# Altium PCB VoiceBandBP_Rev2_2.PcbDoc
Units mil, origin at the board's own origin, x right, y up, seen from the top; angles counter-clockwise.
Board outline 2300 x 3500 mil, 2 copper layers (Top Layer, Bottom Layer), stack 62 mil thick; 53 components, 66 nets, 172 pads, 192 vias.
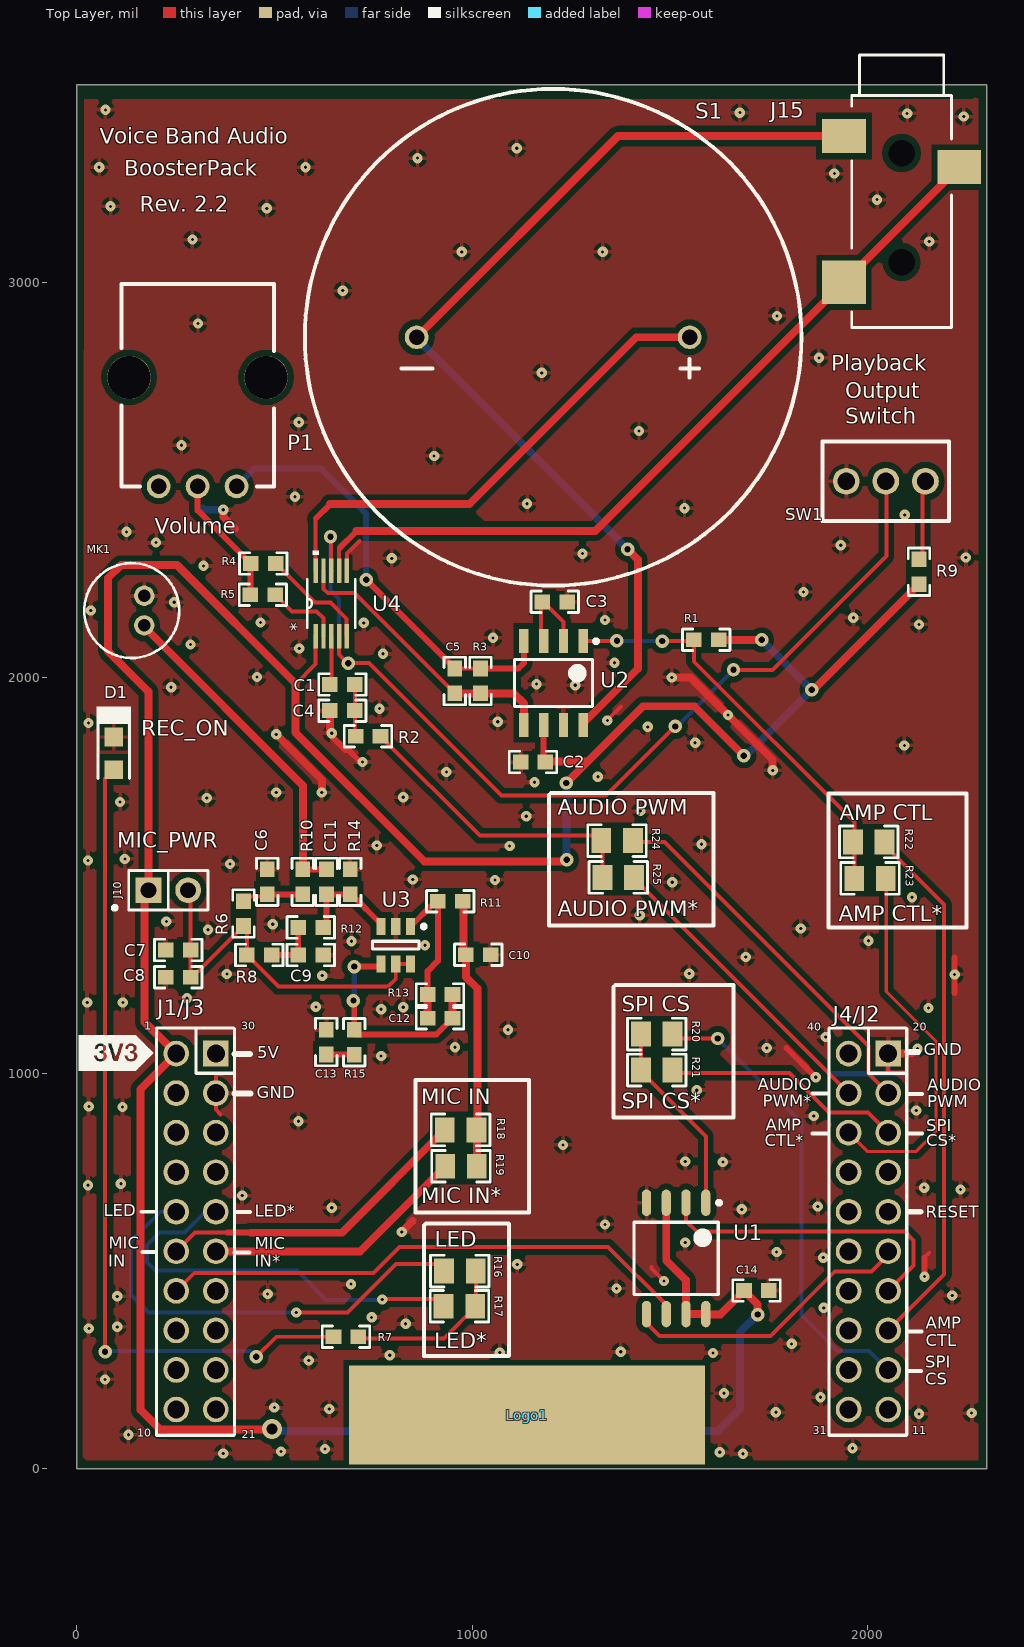
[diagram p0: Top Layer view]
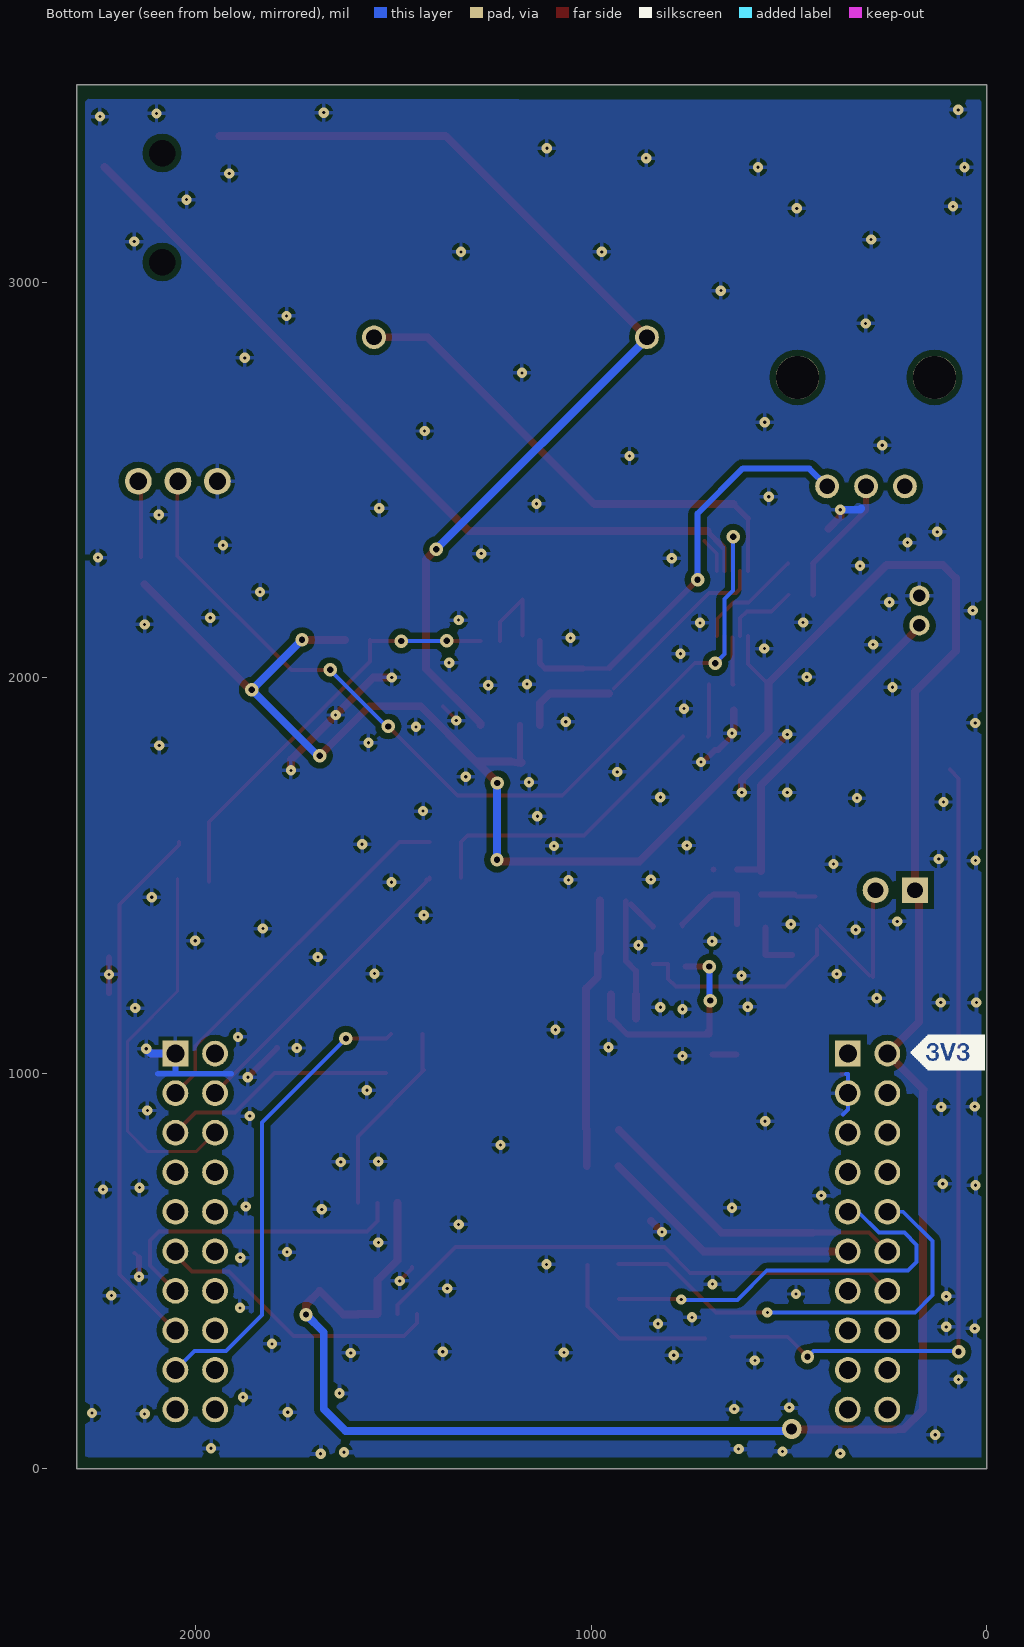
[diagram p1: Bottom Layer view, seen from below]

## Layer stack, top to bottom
Top Solder: solder mask 0.4, Solder Resist, Dk 3.5
Top Layer: signal copper 1.4
Dielectric1: core 59.2, FR-4, Dk 4.8
Bottom Layer: signal copper 1.4
Bottom Solder: solder mask 0.4, Solder Resist, Dk 3.5

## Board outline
0,0 2300,0 2300,3500 0,3500

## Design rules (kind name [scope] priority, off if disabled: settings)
AcuteAngle [All] p1: minimum=4.50000000000000E+0001 checktracksonly=FALSE
AssemblyTestPointUsage [All] p1: valid=2
Clearance Clearance_BoardEdge_MountingHoles [OnCopper and InComponentClass('Mounting Holes') vs IsKeepOut] p1: gap=40
Clearance Clearance_BoardEdge_Poly [OnCopper and InPoly vs IsKeepOut] p2: gap=25
Clearance Clearance_BoardEdge [OnCopper and Not InComponentClass('Logo') and not InComponentClass('FiducialMark') and not InRegion(1000,500,4000,800) and Not IsKeepout vs IsKeepOut] p3: gap=75
Clearance Clearance_Poly [InPolygon] p4: gap=15
Clearance [All] p5: gap=8
ComponentClearance ComponentClearance_Shunt [InComponentClass('Header') vs InComponentClass('Shunt')] p1 off: gap=0 collisioncheckmode=3 verticalgap=0 showdistances=FALSE
ComponentClearance ComponentClearance_Logo [InComponentClass('Logo')] p2 off: gap=50 collisioncheckmode=3 verticalgap=10 showdistances=FALSE
ComponentClearance ComponentClearance_ScrewToNut [(HasFootprint('NY PMS 440 0025 PH')) vs (HasFootprint('Keystone_1902C'))] p3 off: gap=5 collisioncheckmode=3 verticalgap=10 showdistances=FALSE
ComponentClearance ComponentClearance_MountingHoles [InComponentClass('Mounting Holes')] p4 off: gap=250 collisioncheckmode=3 verticalgap=100000 showdistances=FALSE
ComponentClearance ComponentClearance_SmallPassives [HasFootprint('0201*') or HasFootprint('0402*') or HasFootprint('0508') or HasFootprint('0603*') or HasFootprint('0612') or HasFootprint('0805*') or HasFootprint('0815*') or HasFootprint('0830*') or HasFootprint('1206*') or HasFootprint('1210*') or HasFootprint('1808*') or HasFootprint('1812*') or HasFootprint('1825*') or HasFootprint('2010*') or HasFootprint('2220*') or HasFootprint('2225*') or HasFootprint('2512*') or HasFootprint('2728*') or HasFootprint('3518*') vs HasFootprint('0201*') or HasFootprint('0402*') or HasFootprint('0508') or HasFootprint('0603*') or HasFootprint('0612') or HasFootprint('0805*') or HasFootprint('0815*') or HasFootprint('0830*') or HasFootprint('1206*') or HasFootprint('1210*') or HasFootprint('1808*') or HasFootprint('1812*') or HasFootprint('1825*') or HasFootprint('2010*') or HasFootprint('2220*') or HasFootprint('2225*') or HasFootprint('2512*') or HasFootprint('2728*') or HasFootprint('3518*')] p5 off: gap=20 collisioncheckmode=3 verticalgap=10 showdistances=FALSE
ComponentClearance ComponentClearance_THtoSMT [IsThruComponent vs IsSMTComponent] p6 off: gap=100 collisioncheckmode=3 verticalgap=30 showdistances=FALSE
ComponentClearance ComponentClearance_THtoTH [IsThruComponent vs IsThruComponent] p7 off: gap=118.11 collisioncheckmode=3 verticalgap=30 showdistances=FALSE
ComponentClearance [All] p8 off: gap=40 collisioncheckmode=3 verticalgap=10 showdistances=FALSE
DiffPairsRouting [All] p1: maxlimit=100 minlimit=10 mostfreqgap=10 toplayer_minwidth=15 toplayer_maxwidth=15 toplayer_prefwidth=15 bottomlayer_minwidth=15 bottomlayer_maxwidth=15 bottomlayer_prefwidth=15 maxuncoupledlength=1000
FabricationTestPointUsage TestPointUsage [All] p1: valid=2 allowmultiple=FALSE
FabricationTestpoint Testpoint [All] p1: side=3 testpointundercomponent=TRUE minsize=40 maxsize=100 preferedsize=60 minholesize=0 maxholesize=40 preferedholesize=32 testpointgrid=1 allowsidetop=TRUE allowsidebottom=TRUE usegrid=TRUE gridtolerance=0.01
FanoutControl Fanout_LCC [IsLCC] p1: bgadir=Out bgaviamode=Centered fanoutstyle=Auto fanoutdirection=Alternating viagrid=1 // Fanout_LCC (Default Rule)
FanoutControl Fanout_BGA [IsBGA] p2: bgadir=Out bgaviamode=Centered fanoutstyle=Auto fanoutdirection=Alternating viagrid=1 // Fanout_BGA (Default Rule)
FanoutControl Fanout_Default [All] p4: bgadir=Out bgaviamode=Centered fanoutstyle=Auto fanoutdirection=Alternating viagrid=1 // Fanout_Default (Default Rule)
FanoutControl Fanout_Small [(CompPinCount < 5)] p5: bgadir=Out bgaviamode=Centered fanoutstyle=Auto fanoutdirection=OutThenIn viagrid=1 // Fanout_Small (Default Rule)
HoleSize [All] p1: absolutevalues=TRUE maxlimit=251 minlimit=8 maxpercent=80.000 minpercent=20.000
MinimumAnnularRing MinimumAnnularRing_ThermalPadVias [IsVia and InAnyComponent] p1: minimumring=5.91
MinimumAnnularRing [All] p2: minimumring=9
MinimumSolderMaskSliver MinimumSolderMaskSliver_Logo [InComponentClass('Logo') vs InComponentClass('Logo')] p1: minsoldermaskwidth=0.7
MinimumSolderMaskSliver [All] p2: minsoldermaskwidth=3.94
PlaneConnect [All] p1: planeconnectstyle=Relief reliefexpansion=10 reliefentries=4 reliefconductorwidth=10 reliefairgap=10
PolygonConnect PolygonConnect_Logo [HasFootprint('TI_Stacked_SolderMask_Small')] p1: connectstyle=Direct reliefconductorwidth=10 reliefentries=4 polygonreliefangle="90 Angle" airgapwidth=10
PolygonConnect [All] p2: connectstyle=Relief reliefconductorwidth=10 reliefentries=4 polygonreliefangle="90 Angle" airgapwidth=10
RoutingVias ThermalPadVias [IsVia and InAnyComponent] p1: holewidth=7.87 width=19.68 viastyle="Through Hole" minholewidth=7.87 minwidth=19.68 maxholewidth=12.99 maxwidth=23.62
RoutingVias [All] p2: holewidth=16 width=34 viastyle="Through Hole" minholewidth=8 minwidth=26 maxholewidth=40 maxwidth=65
SMDToCorner [All] p1: distance=30000
SilkToSilkClearance [All] p1: silktosilkclearance=5
SilkToSolderMaskClearance SilkscreenOverComponentPads [IsPad] p1: minsilkscreentomaskgap=5 clearancetoexposedcopper=TRUE
SolderMaskExpansion ViaMaskExpansion [IsVia] p1: expansion=-15
SolderMaskExpansion [All] p2: expansion=1.97
UnpouredPolygon [All] p1: allowunpoured=FALSE
Width [All] p1: maxlimit=100 minlimit=6 preferedwidth=10 checkconnectedcopper=TRUE
15 further rules are at their usual default settings.

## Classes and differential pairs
component class Header: J10

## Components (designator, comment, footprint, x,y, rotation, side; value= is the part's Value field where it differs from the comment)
C1 "GRM188R60J474KA01D" 0603 671,1983 r0 top
C2 "GRM188R60J475KE19D" 0603 1153,1787 r0 top
C3 "GRM185R60J105KE26D" 0603 1208,2192 r0 top
C4 "GRM188R60J334KA01D" 0603 671,1917 r180 top
C5 "GRM188R71E182KA01D" 0603 955.32,1992 r90 top
C6 "GRM188R60J475KE19D" 0603 481,1484 r90 top
C7 "GRM188R60J475KE19D" 0603 256,1312 r180 top
C8 "GRM188R70J104KA01D" 0603 256,1243 r180 top
C9 "GRM188R60J474KA01D" 0603 591,1299 r180 top
C10 "GRM188R71C153KA01D" 0603 1014.68,1300 r0 top
C11 "GRM188R61A154KA01D" 0603 631,1484 r270 top
C12 "GRM1885C1H510JA01D" 0603 918,1139 r180 top
C13 "GRM188R60J474KA01D" 0603 630,1079 r270 top
C14 "GRM188R70J104KA01D" 0603 1718,451 r0 top
D1 "LTST-C170KRKT" LED_LTST-C170 93,1809 r90 top
J1/J3 "CRD-081413-A-F" CONN_SSW-110-23-F-D 351,1050 r90 top
J4/J2 "CRD-081413-A-F" CONN_SSW-110-23-F-D 2051,1050 r90 top
J10 "TSW-102-07-G-S" TSW-102-07-G-S 231,1463 r0 top
J15 "SJ-3523-SMT" CUI_SJ-3523-SMT 2085,3185 r270 top
Logo1 "Texas Instruments" TI_Stacked_SolderMask_Small 1138,136 r0 top
MK1 "POM-2242P-C33-R" MIC_POM-2242P-C33-R 170,2170 r270 top
P1 "PTV09A-4015F-A103" Pot1_PCB 305,2484 r0 top
R1 "CRCW060347K0JNEA" 0603 1591,2096 r0 top
R2 "RG1608P-131-B-T5" 0603 736,1852 r180 top
R3 "TNPW06034K02BEEA" 0603 1020.32,1992 r270 top
R4 "TNPW06033K32BEEA" 0603 471,2289 r180 top
R5 "TNPW06033K65BEEA" 0603 470,2210 r180 top
R6 "RC0603FR-07470RL" 0603 421,1404 r90 top
R7 "RC0603FR-071KL" 0603 680,334 r180 top
R8 "RC0603JR-073KL" 0603 461,1299 r180 top
R9 "CRCW060347K0JNEA" 0603 2129,2268 r270 top
R10 "RC0603FR-078K2L" 0603 571,1484 r270 top
R11 "RC0603FR-07820RL" 0603 944,1435 r180 top
R12 "CRCW060347K0JNEA" 0603 591,1369 r180 top
R13 "RC0603FR-07200KL" 0603 918,1199 r0 top
R14 "ERA-3AED513V" 0603 691,1484 r270 top
R15 "RC0603FR-07820RL" 0603 701,1078.68 r270 top
R16 "CRCW08050000Z0EA" 0805_HV 968,500 r180 top
R17 "DNP" 0805_HV 967,411 r180 top
R18 "CRCW08050000Z0EA" 0805_HV 970,857 r180 top
R19 "DNP" 0805_HV 971,765 r180 top
R20 "CRCW08050000Z0EA" 0805_HV 1466,1099 r0 top
R21 "DNP" 0805_HV 1466,1008 r0 top
R22 "CRCW08050000Z0EA" 0805_HV 2002,1585 r0 top
R23 "DNP" 0805_HV 2005,1493 r0 top
R24 "CRCW08050000Z0EA" 0805_HV 1365.55,1588.52 r0 top
R25 "DNP" 0805_HV 1368.55,1495.52 r0 top
S1 "AST-03208MR-R" Speaker 1549,2861 r180 top
SW1 "Used in BOM report" Switch__Toggle 2145,2497 r90 top
U1 "SST25VF016B" "8-SOIC 5.4mm x 5.4mm" 1515,532 r270 top
U2 "TPA301" "8-SOP 1.27mm pitch" 1205,1987 r270 top
U3 "TLV2760_DBV_6" SOT95P280X145-6N 806,1324 r270 top
U4 "TS3A24159_DGS_10" DGS10 643,2188 r90 top

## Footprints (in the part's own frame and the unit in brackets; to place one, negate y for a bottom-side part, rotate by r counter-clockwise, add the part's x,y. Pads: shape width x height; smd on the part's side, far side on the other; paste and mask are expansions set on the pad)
"8-SOIC 5.4mm x 5.4mm" [mm] "SOIC, 8-Leads, Body 5.4x5.4mm (max), Pitch 1.27mm, IPC Medium Density"
  oval 1.7x0.6 smd: 1(-3.575,1.905) 2(-3.575,0.635) 3(-3.575,-0.635) 4(-3.575,-1.905) 5(3.575,-1.905) 6(3.575,-0.635) 7(3.575,0.635) 8(3.575,1.905)
  silkscreen extent -3.7,-2.7 2.33,2.88, body extent -2.7,-2.7 2.7,2.7, height 2.16
"8-SOP 1.27mm pitch" [mm] "SOP, 8-Leads, Body 5.0x4.0mm (max), Pitch 1.27mm, IPC Medium Density"
  rect 1.55x0.6 smd: 1(-2.7,1.905) 2(-2.7,0.635) 3(-2.7,-0.635) 4(-2.7,-1.905) 5(2.7,-1.905) 6(2.7,-0.635) 7(2.7,0.635) 8(2.7,1.905)
  silkscreen extent -2.8,-2.5 1.5,2.85, body extent -2,-2.5 2,2.5, height 1.75
0603 [mm] "0603 from SM-752 data"
  rect 1x0.95 smd: 1(-0.8,0) 2(0.8,0)
  silkscreen extent -1.52,-0.69 1.52,0.69, body extent -0.87,-0.47 0.87,0.47, height 0.85
0805_HV [mil] "0805 with 30mil clearance between pads"
  rect 50x63 smd: 1(-40,0) 2(40,0)
  silkscreen extent -74,-40 74,40, body extent -43,-29 43,29, height 43
CONN_SSW-110-23-F-D [mm] "SAMTEC"
  rect 1.65x1.65 hole 1.15: 1(0,0)
  round 1.65 hole 1.15: 2(0,2.54) 3(-2.54,0) 4(-2.54,2.54) 5(-5.08,0) 6(-5.08,2.54) 7(-7.62,0) 8(-7.62,2.54) 9(-10.16,0) 10(-10.16,2.54) 11(-12.7,0) 12(-12.7,2.54) 13(-15.24,0) 14(-15.24,2.54) 15(-17.78,0) 16(-17.78,2.54) 17(-20.32,0) 18(-20.32,2.54) 19(-22.86,0) 20(-22.86,2.54)
  silkscreen extent -24.51,-1.19 1.65,3.81, body extent -24.43,-1.24 1.57,3.81, height 8.59
CUI_SJ-3523-SMT [mm] "CUI recommended land pattern Rev C CUI_SJ-3523-SMT_Datasheet.pdf"
  rect 2.2x2.8 smd: 1(-4.7,-3.7) 3(-2.7,3.7)
  rect 2.8x2.8 smd: 2(4.7,-3.7)
  round 0 hole 1.7 unplated: 4(-3.6,0) 5(3.4,0)
  silkscreen extent -9.9,-3.2 7.6,3.2, body extent -9.6,-4.5 7.4,4.5, height 5.12
DGS10 [mil]
  rect 62x11 smd: 1(-82.5,39.37) 2(-82.5,19.68) 3(-82.5,0) 4(-82.5,-19.68) 5(-82.5,-39.37) 6(82.5,-39.37) 7(82.5,-19.68) 8(82.5,0) 9(82.5,19.68) 10(82.5,39.37)
  silkscreen extent -61,-61 134,61
LED_LTST-C170 [mm] "LITE-ON"
  rect 1.2x1.2 smd: 1(-1.05,0) 2(1.05,0)
  silkscreen extent -1.6,-1.1 3,1.1, body extent -1.05,-0.67 1.05,0.67, height 1.1
MIC_POM-2242P-C33-R [mm] "POM Audio"
  round 1.3 hole 0.8: 1(-0.95,0) 2(0.95,0)
  silkscreen extent -3.05,-3.85 3.05,2.25, body extent -3.05,-3.84 3.05,2.24, height 2.5
Pot1_PCB [mm]
  round 1.524 hole 1: 1(-2.5,0) 2(0,0) 3(2.5,0)
  round 2.775 hole 2.775: ""(-4.4,7) ""(4.4,7)
  silkscreen extent -4.9,0 4.9,13
SOT95P280X145-6N [mm] "SOT23, 6-Leads, Body 3.0x3.0mm (max), Pitch 0.95mm, IPC Medium Density"
  rect 1.1x0.6 smd: 1(-1.2,0.95) 2(-1.2,0) 3(-1.2,-0.95) 4(1.2,-0.95) 5(1.2,0) 6(1.2,0.95)
  silkscreen extent -1.32,-1.5 0.25,1.93, body extent -0.87,-1.52 0.87,1.53, height 1.45
Speaker [mil]
  round 60 hole 39.37: +(0,0) -(690.16,0)
  silkscreen extent -283,-628 973,628
Switch__Toggle [mm] "SPDT"
  round 1.724 hole 1.1: 1(0,0) 2(0,5.08) Com(0,2.54)
  silkscreen extent -2.54,-1.53 2.54,6.61
TI_Stacked_SolderMask_Small [mil]
  rect 900x250 smd paste-125 mask-125: 0(0,0)
TSW-102-07-G-S [mm] "Samtec 100mil, 1x2, 230 mil above insulator"
  rect 1.65x1.65 hole 1.016 mask+0: 1(-1.27,0)
  round 1.65 hole 1.016 mask+0: 2(1.27,0)
  silkscreen extent -3.56,-1.27 2.54,1.27, body extent -2.54,-1.27 2.54,1.27, height 8.38

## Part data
C1 C9 C13: "CAP, CERM, 0.47uF, 6.3V, +/-10%, X5R, 0603"
C2 C6 C7: "CAP, CERM, 4.7uF, 6.3V, +/-10%, X5R, 0603"
C3: "CAP, CERM, 1uF, 6.3V, +/-10%, X5R, 0603"
C4: "CAP, CERM, 0.33uF, 6.3V, +/-10%, X5R, 0603"
C5: "CAP, CERM, 1800pF, 25V, +/-10%, X7R, 0603"
C8 C14: "CAP, CERM, 0.1uF, 6.3V, +/-10%, X7R, 0603"
C10: "CAP, CERM, 0.015uF, 16V, +/-10%, X7R, 0603"
C11: "CAP, CERM, 0.15uF, 10V, +/-10%, X5R, 0603"
C12: "CAP, CERM, 51pF, 50V, +/-5%, C0G/NP0, 0603"
D1: "LED, Red, SMD"
J1/J3 J4/J2: library part SSW-110-23-F-D, "Connector, Receptacle, 100mil, 10x2, Gold plated, TH"
J10: "Header, TH, 100mil, 2x1, Gold plated, 230 mil above insulator"
J15: "Connector, Audio Jack, 3.5mm, Stereo, SMD"
Logo1: library part TI_Logo, "Texas Instrument Corporate Signature"
MK1: "Microphone, Condenser, Analog, Omnidirectional, -42DB, TH"
P1: library part Pot, "Potentiometer"
R1 R9 R12: "RES, 47k ohm, 5%, 0.1W, 0603"
R2: "RES, 130 ohm, 0.1%, 0.1W, 0603"
R3: library part RT0603BRD074K02L, "RES, 4.02k ohm, 0.1%, 100mW, 0603"
R4: library part RT0603BRD073K32L, "RES, 3.32k ohm, 0.1%, 100mW, 0603"
R5: library part RT0603BRD073K65L, "RES, 3.65k ohm, 0.1%, 100mW, 0603"
R6: "RES, 470 ohm, 1%, 0.1W, 0603"
R7: "RES, 1.00k ohm, 1%, 0.1W, 0603"
R8: "RES, 3.0k ohm, 5%, 0.1W, 0603"
R10: "RES, 8.20k ohm, 1%, 0.1W, 0603"
R11 R15: "RES, 820 ohm, 1%, 0.1W, 0603"
R13: "RES, 200k ohm, 1%, 0.1W, 0603"
R14: library part RT0603DRE0750K5L, "RES, 51kohm, 0.5%, 100mW, 0603"
R16 R18 R20 R22 R24: "RES, 0 ohm, 5%, 0.125W, 0805"
R17 R19 R21 R23 R25: library part CRCW08050000Z0EA, "RES, 0 ohm, 5%, 0.125W, 0805"
S1: library part Speaker, "Speaker"
SW1: library part "Switch -- Toggle"
U1: "16Mbit SPI Flash"
U2: "350mW Mono Audio Power Amplifer"
U3 U4: "Imported"

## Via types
v1: diameter 26, hole 8, Top Layer to Bottom Layer, 172 vias
v2: diameter 34, hole 16, Top Layer to Bottom Layer, 19 vias
v3: diameter 50, hole 28, Top Layer to Bottom Layer, 1 vias

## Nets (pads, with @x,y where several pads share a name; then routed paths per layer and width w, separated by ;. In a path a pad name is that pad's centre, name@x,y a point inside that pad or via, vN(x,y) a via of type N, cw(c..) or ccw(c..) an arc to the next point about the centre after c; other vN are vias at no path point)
+5V: J1/J3.1
\AMP_ON: J4/J2.15 R22.2 | length 1355.5
  Top Layer w10: R22.2 2042,1577 2192,1427 2192,491 J4/J2.15
\AMP_ON_ALT: J4/J2.6 R23.2 | length 954.2
  Top Layer w8: J4/J2.6 1999,802 2121,802 2172,853 2172,1081 2046,1207 R23.2@2046,1493
\CS: J4/J2.17 R20.2 | length 1181.9
  Top Layer w10: R20.2 1517,1088 v2(1620,1088)
  Bottom Layer w10: v2(1620,1088) 1832,876 1832,389 1923,298 2003,298 J4/J2.17
\CS_ALT: J4/J2.5 R21.2 | length 600.5
  Top Layer w10: R21.2@1519,1001 1626,1001 ; 1620,1001 1801,1001 1901,901 2000,901 J4/J2.5
"A\U\D\I\O\ \S\H\U\T\D\O\W\N\": R1.1 R22.1 R23.1 U2.1 | length 1062
  Top Layer w10: U2.1 v2(1365.3,2093.3) v2@1371.3,2093.3 ; v2(1480,2093) R1.1@1556.5,2093 ; R1.1 1559.5,2041.5 1966,1635 R23.1@1966,1485
  Bottom Layer w10: v2(1365.3,2093.3) 1479.7,2093.3 v2(1480,2093)
AUDIO_PWM: R2.1 R24.1 R25.1 | length 757.2
  Top Layer w10: R2.1 1018.5,1601 1313.07,1601 R24.1 ; R25.1 R24.1@1328.55,1585.52
C\E\: R20.1 R21.1 U1.1 | length 495.5
  Top Layer w10: R21.1@1422.71,1008 1590,840.71 U1.1 ; R21.1 R20.1
GND: C2.1 C3.2 C4.2 C6.2 C7.2 C8.2 C9.1 C10.2 C13.1 C14.2 D1.2 J1/J3.3 J4/J2.1 MK1.1 R14.1 SW1.2 U1.4 U2.7 U3.2 U4.6 | length 2003.3
  Top Layer w10: 363.39,896.26 351,908.65 J1/J3.3 351,998 367,998 ; U4.6 682.37,2313.93 713.95,2345.51 ; v1(1341,1892) 1341,1894 1375,1928 ; 1453,510 1453,506 v1(1484,475) ; v1@1859,990 v1(1868,990) ; 2051,1005.5 J4/J2.1 ; 2143,535 2154,546
  Top Layer w15: v1(644,1860) 644,1852.2 678.4,1817.8 686.2,1817.8 717,1787 v1(722,1787) ; R14.1 R14.1@691,1515.8 ; 1794,1064 v1(1868,990) ; v1(2143,486) 2143,535 ; 2219,1203 v1(2219,1250) 2219,1293
  Top Layer w20: v1(370,2425) 370,2407 400,2377 ; v1(504,1857) 619,1742 v1(619,1710) ; C4.2 639.5,1864.5 v1(644,1860) ; v1(821,599) 849,627 ; v1(1504,2001) 1551,2001 1759,1793 v1(1759,1766) ; J4/J2.1 2113,1050
  Bottom Layer w10: J1/J3.3@348.2,947.2 J1/J3.3 ; 355.48,998 351,998 J1/J3.3 ; 363.39,896.26 351,908.65 J1/J3.3
  Bottom Layer w15: 1910,999 2052,999 ; J4/J2.1 2051,1000 2052,999 ; 2095,999 2052,999
  Bottom Layer w20: 317,2428 320,2425 v1(370,2425) ; J4/J2.1 2113,1050 v1(2125,1062)
  other v1: 1684,38 370,39 1625,42 516,44 627,50 1961,52 130,86 2129,139 2262,141 1767,143 638,151 499,155 1880,181 1636,191 71,226 586,274 791,287 1608,293 1069,294 1375,296 1807,316 30,355 102,359 831,367 745,383 1888,407 102,436 2213,438 482,442 1364,456 693,467 1113,517 1887,534 1769,548 1538,572 1335,618 1681,656 644,660 1873,663 418,691 2234,706 2142,711 28,717 111,721 1633,776 1538,777 1229,819 560,879 1863,892 2122,906 115,915 30,916 1567,957 769,1044 1744,1064 956,1066 1893,1092 1090,1110 769,1162 2153,1165 825,1167 604,1168 26,1179 116,1179 278,1190 620,1247 379,1251 1548,1252 1691,1294 880,1324 694,1334 2001,1335 331,1363 1830,1366 495,1377 226,1384 1423,1400 2111,1445 1505,1483 1057,1489 849,1490 387,1529 28,1538 121,1542 1094,1575 758,1576 1579,1579 1136,1650 1425,1663 109,1686 328,1696 825,1698 504,1710 1157,1736 1317,1750 934,1762 2092,1829 1563,1836 1443,1876 29,1886 1064,1889 1646,1906 765,1922 238,1976 1260,1981 1162,1984 455,2002 1359,2038 774,2061 562,2074 287,2084 1052,2101 2129,2135 725,2139 464,2140 1335,2146 1963,2152 35,2170 246,2191 1837,2217 320,2283 796,2302 2247,2304 1278,2314 1931,2335 200,2342 125,2369 2093,2412 1536,2429 1138,2440 551,2458 903,2561 264,2588 1421,2624 561,2646 1175,2771 1876,2809 306,2896 1770,2915 672,2979 973,3077 1329,3077 2155,3103 292,3108 480,3187 85,3192 2023,3209 1915,3275 56,3291 578,3291 861,3314 1112,3339 2242,3419 2099,3427 1676,3429 72,3436
HEAD_OUT: J15.2 J15.3 U4.7 | length 2020.5
  Top Layer w10: U4.7 662.68,2326.68
  Top Layer w15: 664.68,2328.68 706,2370
  Top Layer w20: 706,2371 1310.37,2371 J15.2 J15.3
HEADPHONEG: R4.1 U4.5 | length 280.9
  Top Layer w10: R4.1 505.47,2286.02 601.5,2190 640.5,2190 681.18,2149.32 681.18,2106.69 U4.5
IN+: C3.1 U2.2 U2.3 | length 219.3
  Top Layer w10: U2.3@1173,2107 1173,2198 1230,2141 U2.2
IN-: C5.2 P1.3 R3.1 U2.4 | length 1112.6
  Top Layer w10: C5.2 R3.1
  Top Layer w15: v2(731,2248) C5.2@953.95,2025.05 ; R3.1 1116.5,2023.5 1130,2037 U2.4
  Bottom Layer w15: P1.3 448.11,2528.97 616.5,2529.5 731,2415 v2(731,2248)
J1.2: J1/J3.4
J1.3: J1/J3.6
J1.4: J1/J3.8
J1.8: J1/J3.16
J1.9: J1/J3.18
J1.10: J1/J3.20
J2.11: J4/J2.19
J2.16: J4/J2.9
J2.17: J4/J2.7
J3.23: J1/J3.5
J3.24: J1/J3.7
J3.27: J1/J3.13
J3.28: J1/J3.15
J3.29: J1/J3.17
J3.30: J1/J3.19
J4.31: J4/J2.20
J4.32: J4/J2.18
J4.33: J4/J2.16
J4.34: J4/J2.14
J4.35: J4/J2.12
J4.36: J4/J2.10
J4.37: J4/J2.8
J4.40: J4/J2.2
LED: J1/J3.10 R16.2 | length 1144.4
  Top Layer w10: v1(554.52,395.48) 684.48,395.48 807,518 R16.2@931,518
  Bottom Layer w10: J1/J3.10 211,650 137,576 137,439 180.52,395.48 v1(554.52,395.48)
LED_ALT: J1/J3.9 R17.2 | length 1044.6
  Top Layer w10: v1@772,429 R17.2@930,429
  Bottom Layer w10: J1/J3.9 325,650 272,597 208,597 177,566 177,523 199,501 556,501 630,427 v1@772,427
  other v1: 772,428
M1: C11.1 MK1.2 R10.1 | length 846.6
  Top Layer w15: R10.1 C11.1
  Top Layer w20: MK1.2 170,2129 571,1728 R10.1@571,1512.05
M2: C6.1 R6.2 R10.2 | length 133
  Top Layer w10: R6.2@433.01,1447.5 C6.1@481,1447.5
  Top Layer w15: C6.1@486,1452.5 R10.2
M3: C9.2 R8.1 R12.2 | length 137
  Top Layer w15: R8.1 C9.2 R12.2
M4: C13.2 R15.2 | length 60
  Top Layer w15: C13.2@633,1047.68 R15.2@693,1047.68
M_IN+: C11.2 R12.1 R14.2 U3.3 | length 240.3
  Top Layer w10: U3.3 U3.3@768.6,1377.41
  Top Layer w15: R12.1@631,1377.5 C11.2 R14.2 ; R14.2@698.51,1447.5 U3.3@768.6,1377.41
M_IN-: C12.1 R13.2 R15.1 U3.4 | length 574
  Top Layer w15: v2(699,1184) 701,1182 R15.1@701,1100.35 ; R15.1@701,1098 908.5,1098 C12.1 ; R15.1 R15.1@713.18,1098 ; v2(701,1270) U3.4@761.84,1270
  Top Layer w20: C12.1 R13.2
  Bottom Layer w15: v2@701,1184 v2(701,1270)
MIC: J1/J3.12 R18.2 | length 806.2
  Top Layer w10: J1/J3.12 298,597 380,597
  Top Layer w15: 380,597 440,597
  Top Layer w20: 440,597 670,597 R18.2
MIC_ALT: J1/J3.11 R19.2 | length 669.1
  Top Layer w20: J1/J3.11 716,550 R19.2
MIC_OUT: C10.1 R11.1 R18.1 R19.1 | length 687.7
  Top Layer w20: R11.1@977.18,1437 977.18,1306.01 C10.1 983.18,1243.82 1013,1214 1013,860 1011,858 R19.1
MIC_PWR: C7.1 C8.1 J10.2 R6.1 R8.2 U3.5 U3.6 | length 957.9
  Top Layer w10: J10.2 287.5,1456.5 C7.1 C8.1 ; C8.1@295.75,1247.25 R6.1 ; R6.1@429.5,1364 R8.2 509.5,1219 786,1219 806,1239 U3.5 U3.6
MISO: J4/J2.13 U1.2 | length 796
  Top Layer w10: U1.2 1540,627 1567.02,599.98 2093.02,599.98 2115.5,577.5 2115.5,514.5 J4/J2.13
MOSI: J4/J2.11 U1.5 | length 740.8
  Top Layer w10: U1.5 1440,369 1473,336 1753,336 1916,499 2009,499 2051,541 J4/J2.11
OUT: C12.2 R11.2 R13.1 U3.1 | length 386.4
  Top Layer w15: U3.1 R11.2@899.68,1427.52 ; R13.1 886.5,1258.5 912.5,1284.5 R11.2
  Top Layer w20: C12.2 R13.1
OUTPUT_SIGNAL: C5.1 R3.2 U2.5 U4.9 | length 709.1
  Top Layer w10: U4.9 623.32,2224.68 634,2214 701.82,2214 C5.1@942.82,1973
  Top Layer w20: C5.1 R3.2 1104.5,1960.5 1130,1935 U2.5
P1: P1.2 R4.2 R5.2 | length 328.7
  Top Layer w15: P1.2 305,2423.5 R4.2 ; R5.2 R4.2@438.5,2288
PWM: J4/J2.3 R24.2 | length 945.6
  Top Layer w10: R24.2@1408.86,1585 1485,1585 2001,1069 2001,1000 J4/J2.3
PWM_ALT: J4/J2.4 R25.2 | length 769.9
  Top Layer w10: R25.2 1408.55,1489.52 R25.2@1416.48,1489.52 ; R25.2@1416.48,1484.52 J4/J2.4
REC1: D1.1 R7.2 | length 2083.5
  Top Layer w10: v2(71,296) 71,1745.66 D1.1 ; v2(453,283) 504,334 R7.2@645.57,334
  Bottom Layer w10: v2(71,296) 73,298 438,298 v2(453,283)
RECORD_ON: R7.1 R16.1 R17.1 | length 435.1
  Top Layer w10: R7.1@711.5,330 838,330 928,330 1009,411 R16.1@1009,515
SCK: J1/J3.14 U1.6 | length 1368.6
  Top Layer w10: J1/J3.14 296.48,495.48 749.48,495.48 815,561 1343,561 1490,414 U1.6
SPEAK_OUT: S1.+ U4.10 | length 1267.4
  Top Layer w10: U4.10 603.63,2402.63
  Top Layer w15: 603.63,2402.63 640,2439
  Top Layer w20: 640,2439 992,2439 1414,2861 S1.+
SPEAKERG: R5.1 U4.2 | length 191.6
  Top Layer w10: R5.1 543.5,2168 606,2168 623.32,2150.68 U4.2
"STAGE 1": C1.2 C4.1 R2.2 | length 131.8
  Top Layer w10: C1.2 702.5,1854.01 R2.2
"STAGE 2": C1.1 U4.3 | length 124.4
  Top Layer w10: C1.1 C1.1@643,1986.5 ; C1.1@643,1983 U4.3@643,2102.5
SW1: R9.1 SW1.1 | length 188
  Top Layer w10: R9.1@2138,2305 SW1.1@2138,2493
SWITCH: SW1.Com U4.4 U4.8 | length 2458.4
  Top Layer w10: v2(641,2357) 642.18,2355.82 642.18,2271.32 U4.8 ; U4.4 662.68,2058.32 v2@686,2035 ; v2@686,2031 v2@686,2035 ; v2@1515,1879 1338,1702 1073,1702 738,2037 v2(686,2037) v2@686,2035 ; v2(1660,2020) 1758,2020 2046.5,2308.5 SW1.Com@2046.5,2495.5
  Bottom Layer w10: v2(641,2357) 641,2221 663,2199 663,2060 v2(686,2037) v2@686,2031 ; v2(1513,1877) 1517,1877 v2(1660,2020)
VCC: C2.2 C14.1 J1/J3.2 J10.1 R1.2 R9.2 U1.3 U1.7 U1.8 U2.6 U4.1 | length 8169.2
  Top Layer w10: 552,1983 603.63,2034.63 U4.1
  Top Layer w15: C2.2@1175.5,1786 1180,1790.5 U2.6
  Top Layer w20: 160,959 J1/J3.2 171,1130 171,1453 J10.1 181,1965 78,2068 78,2252 111,2285 253,2285 552,1986 ; 161,959 161,149 210,100 229.61,100 230.09,99.52 v3@493,99.52 ; 552,1983 552,1862 878,1536 v2@1234,1536 ; C2.2@1175.5,1786 1177.5,1784 1202.63,1788 1291,1788 1431,1928 1561,1928 v2(1686,1803) ; v2(1237,1734) 1290,1787 ; U1.3 1490,527 1540,477 U1.7 U1.8 1591,390.25 1626.88,390.57 1686.5,450.15 1721,415.65 v2(1721,390) ; R1.2 v2(1731,2096) ; v2(1858,1970) 1862.5,1970 R9.2
  Bottom Layer w10: v2(1237,1734) v2@1238,1733
  Bottom Layer w20: v3@493,96 1621,96 1676,151 1676,345 v2(1721,390) ; v2(1238,1540) v2@1238,1733 ; v2(1686,1803) 1691,1803 v2(1858,1970) ; v2(1731,2096) v2@1853,1974
  other v3: 493,101
VO-: J15.1 S1.- U2.8 | length 2560.4
  Top Layer w20: S1.- 1367.88,3370.04 J15.1 ; U2.8 1280,1885 1418,2023 1418,2299 v2(1392,2325)
  Bottom Layer w20: S1.- 858.84,2858.16 v2(1392,2325)
pads on no net: J15.4 J15.5 Logo1.0 P1. P1.1

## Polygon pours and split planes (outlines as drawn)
GND on Top Layer "Top Layer-GND" (solid, remove dead copper, pour order 4): 14,19 17,22 2279,22 2279,3477 2265,3463 28,3463 20,3463 18,3461
GND on Bottom Layer "Bottom Layer-GND" (solid, pour order 6): 18,3461 14.01,3457.01 14.01,29.08 2271.92,29.08 2279,22 2279,3463.93

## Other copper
Top Layer:
  pour cut-out: 1535,1072 1536,1071 1602,1071 1657,1016 1543,1016
  pour cut-out: 1048,2008 1048,1980 1046,1978 1052,1972 1123,1972 1123,2010 1129,2016
  pour cut-out: 634,2418 618,2402 618,2395 633,2395 662.65,2365.35 678.35,2365.35 702,2389 1033,2389 1035,2391 1006,2420 1006,2429
  pour cut-out: 878,778 884,778 897,765 707,575 693,575 685,583
  pour cut-out: 179,959 187,951 320,951 320,931.32 353.8,897.52 308.28,852 281,852 252,881 252,151.01 238.5,137.5 238,138 185,138 185,181 174,192
Bottom Layer:
  pour cut-out: 323,2442.75 328.8,2442.75 346.55,2425 373,2451.45 373,2458 354,2477
  pour cut-out: 185,138 239,138 253,152 253,874 284,874 301,857 342,898 351,898 351,904 308.52,946.48 308.52,947.2 188.73,947.2 186.49,949.44 174,936.95 174,192
  pour cut-out: 146,506 195,506 217.14,483.86 206.03,472.76 206.03,415.87 172.13,415.87 148,440 148,447

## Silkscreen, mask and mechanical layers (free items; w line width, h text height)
Top Overlay:
  drawing of 334 lines, arcs and shapes, not listed
  text "Voice Band Audio" at 57,3350 h40
  text "BoosterPack" at 120,3270 h40
  text "Rev. 2.2" at 159,3179 h40
  text "Playback" at 1907,2776 h40
  text "Output" at 1943,2707 h40
  text "Switch" at 1943,2642 h40
  text "Volume" at 196,2364 h40
  text "REC_ON" at 163,1854 h40
  text "AUDIO PWM" at 1215,1654 h40
  text "AMP CTL" at 1928,1640 h40
  text "MIC_PWR" at 102,1570 h40
  text "AUDIO PWM*" at 1216,1397 h40
  text "AMP CTL*" at 1926,1385 h40
  text "SPI CS" at 1378,1156 h40
  text "1" at 170,1110 h20
  text "30" at 415,1110 h20
  text "40" at 1846,1108 h20
  text "20" at 2113,1108 h20
  text "GND" at 2141.58,1045.42 h30
  text "5V" at 456,1038 h30
  text "AUDIO" at 1721,957 h30
  text "AUDIO" at 2150,956 h30
  text "GND" at 455,937 h30
  text "MIC IN" at 871,922 h40
  text "PWM*" at 1734,915 h30
  text "PWM" at 2150,914 h30
  text "SPI CS*" at 1378,911 h40
  text "AMP" at 1741,855 h30
  text "SPI" at 2147,854 h30
  text "CTL*" at 1739,816 h30
  text "CS*" at 2147,815 h30
  text "MIC IN*" at 870,672 h40
  text "LED" at 68,638 h30
  text "LED*" at 449,637 h30
  text "RESET" at 2146,635 h30
  text "LED" at 905,562 h40
  text "MIC" at 80,556 h30
  text "MIC" at 450,555 h30
  text "IN" at 79,511 h30
  text "IN*" at 450,511 h30
  text "AMP" at 2146,354 h30
  text "CTL" at 2146,310 h30
  text "LED*" at 903,305 h40
  text "SPI" at 2145,255 h30
  text "CS" at 2145,213 h30
  text "31" at 1860,87 h20
  text "11" at 2112,87 h20
  text "10" at 152.46,81 h20
  text "21" at 417,77 h20
Bottom Overlay:
  drawing of 295 lines, arcs and shapes, not listed
M1 Board Outline:
  the board outline again, w10
M2 Board Dimensions:
  rectangle: 124.5,-410.5 499.5,-285.5
  rectangle: -0.5,-285.5 124.5,-160.5
  lines w7: -0.5,-285.5 999.5,-285.5 ; 124.5,-410.5 124.5,-160.5 ; 249.5,-410.5 249.5,-160.5 ; 499.5,-410.5 499.5,-160.5 ; 749.5,-410.5 749.5,-160.5 ; -0.5,-410.5 -0.5,-160.5 999.5,-160.5 999.5,-410.5 -0.5,-410.5
  lines w10: -0.5,-475.5 -0.5,-455.5 ; 59.5,-485.5 -0.5,-465.5 ; 59.5,-445.5 -0.5,-465.5 ; 223.58,-465.5 -0.5,-465.5 ; 775.42,-465.5 999.5,-465.5 ; 939.5,-485.5 999.5,-465.5 ; 939.5,-445.5 999.5,-465.5 ; 999.5,-475.5 999.5,-455.5
  text "1000 (mil)" at 233.58,-501.49 h60
M5 Assembly Top:
  lines w10: -292,-930.17 6308,-930.17 ; -292,-726.83 6310,-726.83 ; -292,-523.5 -292,-1133.5 3713,-1133.5 6310,-1133.5 6310,-523.5 -291.5,-523.5 -291.5,-1133.5 1284,-1133.5 ; 2173,-1133.5 2173,-523.5 ; 3440,-726.83 3440,-523.5 ; 4280,-726.83 4280,-523.5 ; 4902,-1140 4902,-937.17
  text "COMPONENTS MARKED 'DNP' SHOULD NOT BE POPULATED." at 1153.5,-318.5 h60
  text "ASSEMBLY VARIANT:" at 1153,-434 h60
  text ".VariantName" at 2189,-434 h60
  text "PCB VIEWED FROM TOP SIDE" at -228.5,-655.67 h60
  text "BOARD #:" at 2248,-655.67 h60
  text ".PRJ_Number" at 2793.5,-655.67 h60
  text "REV:" at 3638,-655.67 h60
  text ".PCB_Rev" at 3929.5,-655.67 h60
  text "SVN REV:" at 4476,-655.67 h60
  text ".VersionControl_RevNumber" at 4982,-655.67 h60
  text "IGNORE ->" at -228.5,-858.49 h60
  text "PLOT NAME =" at -228.5,-1064.34 h60
  text ".plot_File_Name" at 577,-1064.34 h60
  text "GENERATED    :" at 2250,-1064.34 h60
  text ".Print_Date" at 3119.5,-1064.34 h60
  text ".Print_Time" at 3848.5,-1064.34 h60
  text "TEXAS INSTRUMENTS" at 5113,-1064.34 h60
M6 Assembly Bottom:
  lines w10: -292.5,-727.33 6309.5,-727.33 ; -290.5,-930.67 6309.5,-930.67 ; 1115.5,-1140.5 1115.5,-937.67 ; 1737.5,-727.33 1737.5,-524 ; 2577.5,-727.33 2577.5,-524 ; 3844.5,-1134 3844.5,-524 ; 4733.5,-1134 6309,-1134 6309,-524 -292.5,-524 -292.5,-1134 2304.5,-1134 6309.5,-1134 6309.5,-524
  text "COMPONENTS MARKED 'DNP' SHOULD NOT BE POPULATED." at 6102,-318 h60
  text ".VariantName" at 5058,-434 h60
  text "ASSEMBLY VARIANT:" at 6097,-434 h60
  text ".VersionControl_RevNumber" at 1035.5,-656.17 h60
  text "SVN REV:" at 1541.5,-656.17 h60
  text ".PCB_Rev" at 2088,-656.17 h60
  text "REV:" at 2379.5,-656.17 h60
  text ".PRJ_Number" at 3224,-656.17 h60
  text "BOARD #:" at 3769.5,-656.17 h60
  text "PCB VIEWED FROM BOTTOM SIDE" at 6246,-656.17 h60
  text "IGNORE ->" at 2547.85,-858.49 h60
  text "TEXAS INSTRUMENTS" at 904.5,-1064.84 h60
  text ".Print_Time" at 2169,-1064.84 h60
  text ".Print_Date" at 2898,-1064.84 h60
  text "GENERATED    :" at 3767.5,-1064.84 h60
  text ".plot_File_Name" at 5440.5,-1064.84 h60
  text "PLOT NAME =" at 6246,-1064.84 h60
M9 Title Sheet:
  drawing of 54 lines, arcs and shapes, not listed
  text "1" at 739.84,8036.5 h70
  text "2" at 3235.5,8036.5 h70
  text "3" at 5724.84,8036.5 h70
  text "4" at 8231.51,8036.5 h70
  text "5" at 10730.5,8036.5 h70
  text "6" at 13235.5,8036.5 h70
  text "A" at -416.5,6893.5 h70
  text "A" at 14383.5,6893.5 h70
  text "B" at -416.5,4513.5 h70
  text "B" at 14383.5,4513.5 h70
  text "C" at -416.5,2138.5 h70
  text "C" at 14383.5,2138.5 h70
  text ".PRJ_Title" at 11393.5,144.17 h70
  text "DESIGNED FOR:" at 11343.5,-23.5 h45
  text ".PRJ_Customer" at 11393.5,-163.5 h70
  text "D" at -416.5,-231.5 h70
  text "D" at 14383.5,-231.5 h70
  text "FILE NAME:" at 11343.5,-323.5 h45
  text ".PCB_File_Name_No_Path" at 11393.5,-443.5 h70
  text "Texas Instruments (TI) and/or its licensors do not warrant the accuracy or completeness of this specification" at 6374,-605.34 h45
  text "ENGINEER:" at 11343.5,-613.5 h45
  text "LAYOUT BY:" at 12848.5,-613.5 h45
  text "or any information contained therein. TI and/or its licensors do not warrant that this design will meet" at 6329.01,-718 h45
  text ".PRJ_Engineer" at 11393.5,-768.49 h70
  text ".PCB_Layout" at 12899,-768.49 h70
  text "the specifications, will be suitable for your application or fit for any particular purpose, or will operate in" at 6329.01,-830.67 h45
  text ".Layer_Name" at 577,-858.49 h60
  text "ALTIUM DESIGNER VERSION:" at 12848.5,-923.5 h45
  text "an implementation. TI and/or its licensors do not warrant that the design is production worthy. You should" at 6329.01,-943.33 h45
  text "completely validate and test your design implementation to confirm the system functionality for your application." at 6374,-1056 h45
  text ".print_Scale" at 11393.5,-1056.83 h70
  text ".Application_BuildNumber" at 12899,-1056.83 h70
  text "1" at 739.84,-1263.5 h70
  text "2" at 3235.5,-1263.5 h70
  text "3" at 5724.84,-1263.5 h70
  text "4" at 8231.51,-1263.5 h70
  text "5" at 10730.5,-1263.5 h70
  text "6" at 13235.5,-1263.5 h70
M10 Fab Notes:
  drawing of 212 lines, arcs and shapes, not listed
  text "DESIGN INFORMATION" at 12381.02,6810 h60
  text "(REFER ALSO ARRAY/PANEL PROFILING INFORMATION)" at 12019.46,6648.29 h60
  text "BOARD SIZE" at 11333.46,6644 h60
  text "3450MIL" at 11795.78,6516.18 h60
  text "X" at 12301.46,6516.18 h60
  text "4950MIL" at 12532.78,6516.18 h60
  text "Number of Layers :" at 11736.46,6319 h60
  text "2" at 12831.27,6309 h60
  text "MIN. TRACK WIDTH:" at 11736.46,6180 h60
  text "8" at 12832.7,6180 h60
  text "MIL" at 12987.46,6180 h60
  text "MIN. CLEARANCE:" at 11736.46,6048 h60
  text "8" at 12832.7,6048 h60
  text "MIL" at 12987.46,6048 h60
  text "MIN. VIA PAD SIZE:" at 11736.46,5916 h60
  text "24" at 12802.71,5916 h60
  text "MIL" at 12987.46,5916 h60
  text "0.05mm (2MIL)" at 12431.46,5774.29 h60
  text "MINIMUM ANNULAR RING" at 11407.23,5770 h60
  text "EXTERNAL" at 13139.46,5770 h60
  text "PER" at 11607.23,5652 h60
  text "IPC-D-275 CLASS 2 LEVEL C" at 11827.23,5652 h60
  text "MIL, HOLES" at 13315.46,5539.71 h60
  text "+/-" at 12923,5539 h60
  text "+/-" at 13777,5539 h60
  text "REGISTRATION TOLERANCES:" at 11407.23,5534 h60
  text "METAL" at 12607,5534 h60
  text "5" at 13183.2,5534 h60
  text "3" at 14016.2,5534 h60
  text "MIL" at 14132.46,5534 h60
  text "MATERIAL:" at 11332.46,5324.54 h60
  text "FR-4 High Tg" at 12318.9,5184.21 h60
  text "FR-408" at 11753.46,5175.64 h60
  text "X" at 12165.46,5175.64 h60
  text "OTHER" at 13241.46,5175.64 h60
  text "62 MIL (1.6mm) +/-10%" at 12073.56,5012.92 h60
  text "THICKNESS:" at 11407.23,5008.64 h60
  text "X" at 11945.4,5008.64 h60
  text "OTHER" at 13358.46,5008.64 h60
  text "TOLERANCE:" at 11407.23,4850.64 h60
  text "X" at 12246.53,4850.64 h60
  text "ANSI IPC-6012 TYPE 3 CLASS 2" at 12433.48,4850.64 h60
  text "OTHER +/-" at 12433.46,4694.64 h60
  text "BOW & TWIST:" at 11407.23,4537.64 h60
  text "X" at 12246.53,4537.64 h60
  text "ANSI IPC-6012 TYPE 3 CLASS 2" at 12433.48,4537.64 h60
  text "OTHER +/-" at 12433.46,4379.13 h60
  text "COPPER THICKNESS (FINISHED):" at 11332.46,4243.64 h60
  text "1.4MIL (1oz)" at 12212.46,4090.92 h60
  text "2MIL (1.4oz)" at 12979.46,4090.92 h60
  text "2.8MIL (2oz)" at 13706.46,4090.92 h60
  text "OUTER:" at 11689.46,4086.64 h60
  text "X" at 12084,4086 h60
  text "1.4MIL (1oz)" at 12212.46,3933.92 h60
  text "2.8MIL (2oz)" at 12979.46,3933.92 h60
  text "N/A" at 13706,3934.29 h60
  text "INNER SIGNAL:" at 11400.38,3929.64 h60
  text "X" at 12085.42,3929.64 h60
  text "DRILLING:" at 11332.46,3790.64 h60
  text "REFERENCE:" at 11407.23,3673.64 h60
  text "X" at 12055.46,3673.64 h60
  text "AS SHOWN" at 12242.46,3673.64 h60
  text "X" at 12956.46,3673.64 h60
  text "NC_DRILL FILES" at 13093.46,3673.64 h60
  text "PTH MIN COPPER THICKNESS:" at 11407.23,3515.64 h60
  text "X" at 12757.46,3515.64 h60
  text "1MIL" at 12894.46,3515.64 h60
  text "OTHER" at 13391.46,3515.64 h60
  text "BOARD FINISH:" at 11332.46,3356.64 h60
  text "SILKSCREEN:" at 11487.68,3238.64 h60
  text "X" at 12436.46,3238.64 h60
  text "TOP" at 12562.46,3238.64 h60
  text "X" at 12946.46,3238.64 h60
  text "BOTTOM" at 13073.46,3238.64 h60
  text "SILKSCREEN COLOR:" at 11487.68,3071.64 h60
  text "X" at 12435.42,3071.64 h60
  text "WHITE" at 12562.46,3071.64 h60
  text "OTHER" at 13073.46,3071.64 h60
  text "SOLDER RESIST COLOR:" at 11487.68,2901.64 h60
  text "X" at 12055.42,2742.44 h60
  text "GREEN" at 12182.46,2742.44 h60
  text "BLUE" at 12773.46,2742.44 h60
  text "OTHER" at 13311.46,2742.44 h60
  text "IMMERSION GOLD (ENIG)" at 12393.46,2553.92 h60
  text "ENEPIG" at 13731,2550.64 h60
  text "SURFACE FINISH:" at 11332.46,2549.64 h60
  text "X" at 12206.51,2549.64 h60
  text "IMM. TIN/SILVER OR EQUIV" at 11662,2392.64 h60
  text "OTHER" at 13093.46,2392.64 h60
  text "ARRAY/PANEL:" at 11332.46,2213.64 h60
  text "CUT AND TRIM PER MECH LAYER 1" at 12393.46,2209.35 h60
  text "N.C. ROUTE" at 12393.46,2057.64 h60
  text "X" at 13072.46,2057.64 h60
  text "V. SCORE" at 13259.46,2057.64 h60
  text "CERTIFICATION:" at 11332.46,1920.64 h60
  text "MATERIALS AND WORKMANSHIP FOR ALL PCBS" at 12057.46,1920.64 h60
  text "TO MEET OR EXCEED THE REQUIREMENTS OF:" at 12057.46,1822.64 h60
  text "X" at 11683.96,1686.13 h60
  text "ANSI IPC-A-600F CLASS ->" at 11822.96,1686.13 h60
  text "X" at 13462.02,1686.13 h60
  text "2" at 13580.96,1686.14 h60
  text "1" at 13265.96,1684.64 h60
  text "3" at 13934.96,1684.64 h60
  text "X" at 11686.02,1526.64 h60
  text "UL 94V-0" at 11822.96,1526.64 h60
  text "X" at 12498.02,1526.64 h60
  text "RoHS" at 12634.96,1526.64 h60
  text "OTHER" at 13279.36,1526.64 h60
  text "PER ORDER" at 13676.42,1526.64 h60
  text "ADDITIONAL REQUIREMENTS:" at 11332.46,1385.64 h60
  text "YES" at 12312.96,1270.64 h60
  text "REQUIRED" at 13174.46,1114.49 h60
  text "BARE BOARD ELEC. TEST:" at 11407.23,1111.64 h60
  text "NONE" at 12712.96,1111.64 h60
  text "X" at 13047.46,1111.64 h60
  text "PER ORDER" at 13766.46,1111.64 h60
  text "MANUFACTURER'S UL:" at 11407.23,954.64 h60
  text "RAIL" at 12572.96,950.35 h60
  text "METAL" at 13064.77,950.35 h60
  text "X" at 13440,950 h60
  text "SILK" at 13576.46,950.35 h60
  text ".Layer_Name" at 577,-858.49 h60
M11 Gerber Information:
  lines w10: -292,-930.17 6308,-930.17 ; -292,-726.83 6310,-726.83 ; -292,-523.5 -292,-1133.5 3713,-1133.5 6310,-1133.5 6310,-523.5 -291.5,-523.5 -291.5,-1133.5 1284,-1133.5 ; 2173,-1133.5 2173,-523.5 ; 3440,-726.83 3440,-523.5 ; 4280,-726.83 4280,-523.5 ; 4902,-1140 4902,-937.17
  text "ALL ARTWORK VIEWED FROM TOP SIDE" at -228.5,-655.67 h60
  text "BOARD #:" at 2248,-655.67 h60
  text ".PRJ_Number" at 2793.5,-655.67 h60
  text "REV:" at 3638,-655.67 h60
  text ".PCB_Rev" at 3929.5,-655.67 h60
  text "SVN REV:" at 4476,-655.67 h60
  text ".VersionControl_RevNumber" at 4982,-655.67 h60
  text "LAYER NAME =" at -228.5,-858.49 h60
  text "PLOT NAME =" at -228.5,-1064.34 h60
  text ".plot_File_Name" at 577,-1064.34 h60
  text "GENERATED    :" at 2250,-1064.34 h60
  text ".Print_Date" at 3119.5,-1064.34 h60
  text ".Print_Time" at 3848.5,-1064.34 h60
  text "TEXAS INSTRUMENTS" at 5113,-1064.34 h60
M12 Stackup:
  lines w6: 11360,7460 13910,7460 ; 11360,7564.4 13910,7564.4 ; 11300,6975 ccw(c11334,6975) 11334,6941 13936,6941 ccw(c13936,6975) 13970,6975 13970,7681 ccw(c13936,7681) 13936,7715 11334,7715 ccw(c11334,7681) 11300,7681 11300,6975
  text "The Stackup Legend below this is static." at 11605.5,7874.5 h60
  text "If you change the stackup, update the Legend." at 11615.5,7784.5 h60
  text "Layer Stack Up Detail for: Ref_Design.PcbDoc" at 11360,7597.1 h57
  text "Layer" at 11360,7525.4 h24
  text "Gerber" at 12255.81,7525.4 h24
  text "Copper" at 12819.33,7525.4 h24
  text "Dielectric" at 13422.04,7525.4 h24
  text "Name" at 11360,7477.4 h24
  text "Document" at 12255.81,7477.4 h24
  text "Thickness" at 12819.33,7477.4 h24
  text "Material" at 13422.04,7477.4 h24
  text "Top Solder Mask" at 11360,7384.44 h34
  text "(.GTS)" at 12255.81,7384.44 h34
  text "Solder Resist" at 13422.04,7384.44 h34
  text "Top Layer" at 11360,7287.69 h34
  text "(.GTL)" at 12255.81,7287.69 h34
  text "1.4mil" at 12819.33,7287.69 h34
  text "FR-4" at 13422.04,7239.31 h34
  text "Bottom Layer" at 11360,7190.94 h34
  text "(.GBL)" at 12255.81,7190.94 h34
  text "1.4mil" at 12819.33,7190.94 h34
  text "Bottom Solder Mask" at 11360,7094.19 h34
  text "(.GBS)" at 12255.81,7094.19 h34
  text "Solder Resist" at 13422.04,7094.19 h34
  text ".Layer_Name" at 577,-858.49 h60
M15 Courtyards Top:
  text ".Layer_Name" at 577,-858.49 h60
M16 Courtyards Bottom:
  text ".Layer_Name" at 577,-858.49 h60

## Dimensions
2098,87 to 2300,0 on M2 Board Dimensions
398,87 to 0,0 on M2 Board Dimensions
351,1050 to 2051,1050 on M2 Board Dimensions
0,0 to 2300,0 on M2 Board Dimensions
0,0 to 0,3500 on M2 Board Dimensions
201,85 to 0,0 on M2 Board Dimensions
2098,87 to 2300,0 on M2 Board Dimensions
